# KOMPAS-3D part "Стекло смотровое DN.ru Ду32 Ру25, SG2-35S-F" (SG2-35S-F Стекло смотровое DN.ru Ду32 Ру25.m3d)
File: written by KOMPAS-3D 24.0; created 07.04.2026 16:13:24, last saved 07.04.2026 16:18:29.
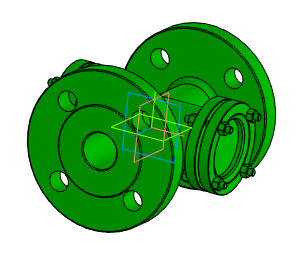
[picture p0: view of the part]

Document properties: Автор: Main; Полное имя файла: D:\DN.ru Аутсерс\Стекло смотровое DN.ru\SG2-35S-F Стекло смотровое DN.ru Ду32 Ру25\SG2-35S-F Стекло смотровое DN.ru Ду32 Ру25.m3d

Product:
- Body: Тело 1  | qty 1
    Масса: 6.03947
- Part/product: Стекло смотровое DN.ru Ду32 Ру25  | designation SG2-35S-F
    Масса: 6.2
    Раздел спецификации: Прочие изделия
    Примечание: D500-00094

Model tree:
1. Операция без истории:1

Expressions: SG2-35S-F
